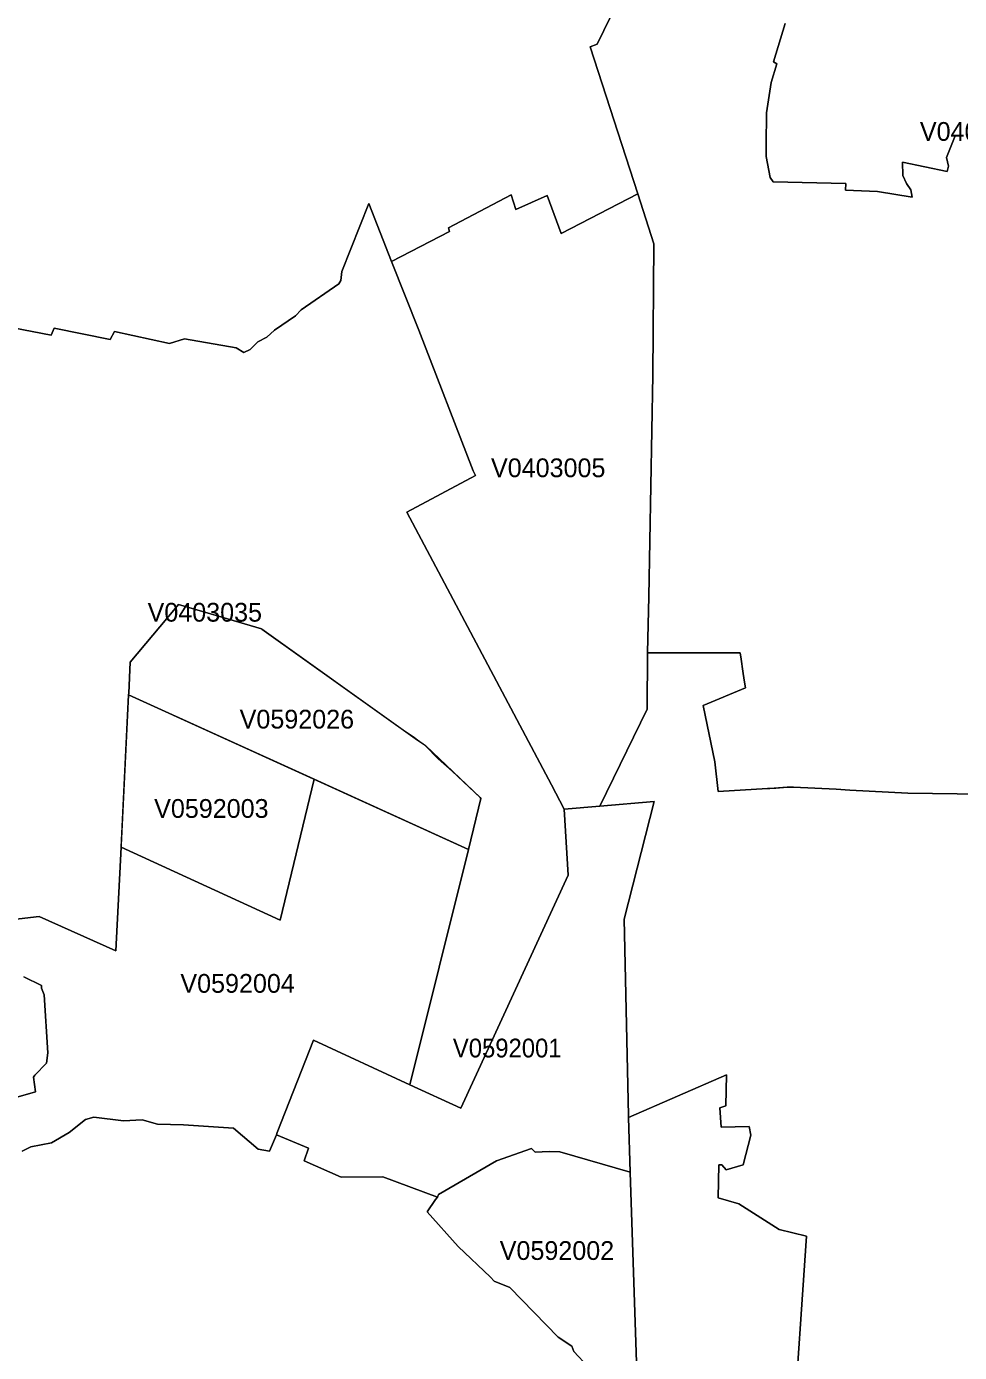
# Model space of a CAD drawing. Extents: x 369010 to 735936, y 6377141 to 6616555.
# Drawn here: x 420443 to 425415, y 6476077 to 6483144 of the extents above; entities that cross this region are included whole.
import ezdxf
from ezdxf.enums import TextEntityAlignment as Align

# ---------------------------------------------------------------- set-up
doc = ezdxf.new("R2010")
doc.units = 0
doc.header["$LTSCALE"] = 40
doc.layers.add('3', color=7, linetype='Continuous', lineweight=13)
doc.layers.add('4', color=7, linetype='Continuous')

msp = doc.modelspace()

# ---------------------------------------------------------------- linework, layer by layer
at = {"layer": '3'}
for points in [[(420168.49, 6481577.82), (420573.64, 6481498.71), (420590.69, 6481536.61), (420888.59, 6481475.2), (420911.43, 6481517.74), (421204.37, 6481454.85), (421284.81, 6481479.01), (421560.54, 6481431.84), (421600.92, 6481406.52), (421635.02, 6481422.74), (421675.4, 6481463.29), (421724.22, 6481488.11), (421764.77, 6481526.01), (421877.15, 6481601.81), (421906.61, 6481633.76), (422108.52, 6481772.78), (422118.29, 6481790.99), (422123.58, 6481837.33), (422267.74, 6482199.78), (422388.89, 6481892.11), (422698.21, 6482051.82), (422692.42, 6482070.69), (423026.08, 6482247.28), (423050.9, 6482169), (423218.06, 6482242.65), (423292.37, 6482041.23), (423700.67, 6482252.25), (423447.12, 6483035.08), (423484.69, 6483050.47), (423555.19, 6483195.45)], [(423555.19, 6483195.45), (423484.69, 6483050.47), (423447.12, 6483035.08), (423700.67, 6482252.25), (423787.23, 6481985.29), (423781.93, 6481286.36), (423759.92, 6480105.49), (423752.31, 6479805.6), (424246.01, 6479805.27), (424251.14, 6479771.67), (424260.9, 6479707.62), (424268.18, 6479660.29), (424274.31, 6479619.9), (424048.56, 6479524.57), (424111.29, 6479224.02), (424129.16, 6479066.96), (424392.15, 6479083.34), (424404.89, 6479082.68), (424436.01, 6479085.33), (424496.58, 6479089.46), (424530.51, 6479090.13), (424757.91, 6479079.37), (424831.56, 6479073.74), (425140.39, 6479058.35), (425534.95, 6479052.39)], [(425422.41, 6482558.92), (425392.95, 6482561.57), (425346.11, 6482445.06), (425357.2, 6482400.04), (425349.92, 6482370.58), (425111.1, 6482421.06), (425113.08, 6482350.39), (425132.45, 6482307.36), (425155.95, 6482272.77), (425163.23, 6482234.87), (424978.53, 6482265.32), (424808.39, 6482271.44), (424809.05, 6482306.7), (424421.61, 6482316.13), (424407.21, 6482338.31), (424385.69, 6482451.35), (424384.53, 6482513.58), (424387.02, 6482684.38), (424411.84, 6482845.58), (424441.63, 6482944.05), (424424.75, 6482956.3), (424486.98, 6483159.21)], [(424486.98, 6483159.21), (424424.75, 6482956.3), (424441.63, 6482944.05), (424411.84, 6482845.58), (424387.02, 6482684.38), (424384.53, 6482513.58), (424385.69, 6482451.35), (424407.21, 6482338.31), (424421.61, 6482316.13), (424809.05, 6482306.7), (424808.39, 6482271.44), (424978.53, 6482265.32), (425163.23, 6482234.87), (425155.95, 6482272.77), (425132.45, 6482307.36), (425113.08, 6482350.39), (425111.1, 6482421.06), (425349.92, 6482370.58), (425357.2, 6482400.04), (425346.11, 6482445.06), (425392.95, 6482561.57), (425422.41, 6482558.92)], [(420220.62, 6478366.87), (420511.41, 6478401.3), (420919.87, 6478217.26), (420947.18, 6478770.54), (420987.07, 6479582.67), (420987.56, 6479591.44), (420995.67, 6479755.62), (421236.98, 6480043.76), (421252.87, 6480062.79), (421253.03, 6480063.12), (421393.38, 6480022.08), (421694.76, 6479933.87), (421695.09, 6479933.87), (421697.41, 6479932.21), (422527.58, 6479340.86), (422564.32, 6479316.37), (422569.62, 6479310.91), (422571.27, 6479309.75), (422860.08, 6479035.01), (422865.21, 6479030.21), (422798.01, 6478758.29), (422486.2, 6477503.44), (422757.3, 6477378.65), (423330.27, 6478621.25), (423308.76, 6478971.79), (423241.73, 6479102.04), (422470.48, 6480554.84), (422835.58, 6480751.62), (422823.83, 6480775.12), (422533.37, 6481525.52), (422388.89, 6481892.11), (422267.74, 6482199.78), (422123.58, 6481837.33), (422118.29, 6481790.99), (422108.52, 6481772.78), (421906.61, 6481633.76), (421877.15, 6481601.81), (421764.77, 6481526.01), (421724.22, 6481488.11), (421675.4, 6481463.29), (421635.02, 6481422.74), (421600.92, 6481406.52), (421560.54, 6481431.84), (421284.81, 6481479.01), (421204.37, 6481454.85), (420911.43, 6481517.74), (420888.59, 6481475.2), (420590.69, 6481536.61), (420573.64, 6481498.71), (420168.49, 6481577.82)], [(423752.31, 6479805.43), (423751.48, 6479505.71), (423499.09, 6478988.18), (423788.06, 6479013.83), (423628.84, 6478386.07), (423650.69, 6477340.58), (423651.02, 6477330.16), (424174.51, 6477556.07), (424169.38, 6477391.23), (424138.1, 6477380.8), (424146.04, 6477278.35), (424294.5, 6477280.84), (424303.77, 6477235.16), (424262.89, 6477076.6), (424171.53, 6477050.46), (424148.03, 6477076.6), (424132.31, 6477076.6), (424130.15, 6476901.67), (424239.55, 6476869.39), (424453.71, 6476732.19), (424600.35, 6476696.77), (424528.03, 6475631.92)], [(425534.95, 6479052.39), (425140.39, 6479058.35), (424831.56, 6479073.74), (424757.91, 6479079.37), (424530.51, 6479090.13), (424496.58, 6479089.46), (424404.89, 6479082.68), (424392.15, 6479083.34), (424129.16, 6479066.96), (424111.29, 6479224.02), (424048.56, 6479524.57), (424274.31, 6479619.9), (424268.18, 6479660.29), (424260.9, 6479707.62), (424251.14, 6479771.67), (424246.01, 6479805.1), (423752.31, 6479805.43)], [(420419.55, 6477150.75), (420466.56, 6477172.93), (420576.12, 6477193.95), (420670.13, 6477250.05), (420757.51, 6477317.91), (420802.7, 6477331.65), (420960.59, 6477312.12), (421059.72, 6477316.09), (421141.98, 6477293.75), (421280.34, 6477289.94), (421546.47, 6477273.39), (421677.05, 6477161.18), (421738.29, 6477150.75), (421774.87, 6477236.48), (421778.67, 6477249.56), (421973.31, 6477741.77), (422486.2, 6477503.44), (422486.2, 6477503.44), (422486.2, 6477503.44), (422798.01, 6478758.29), (421976.45, 6479132.33), (421976.45, 6479132.16), (421795.55, 6478380.78), (420947.18, 6478770.54), (420919.87, 6478217.26), (420511.41, 6478401.3), (420220.62, 6478366.87)], [(420198.28, 6477383.12), (420491.88, 6477465.37), (420480.13, 6477543.82), (420487.91, 6477554.25), (420550.47, 6477618.13), (420557.09, 6477674.41), (420537.56, 6477983.9), (420523.33, 6478017.83), (420523.33, 6478033.55), (420428.16, 6478078.73)], [(420428.16, 6478078.73), (420523.33, 6478033.55), (420523.33, 6478017.83), (420537.56, 6477983.9), (420557.09, 6477674.41), (420550.47, 6477618.13), (420487.91, 6477554.25), (420480.13, 6477543.82), (420491.88, 6477465.37), (420198.28, 6477383.12)], [(424528.03, 6475631.92), (424600.35, 6476696.77), (424453.71, 6476732.19), (424239.55, 6476869.39), (424130.15, 6476901.67), (424132.31, 6477076.6), (424148.03, 6477076.6), (424171.53, 6477050.46), (424262.89, 6477076.6), (424303.77, 6477235.16), (424294.5, 6477280.84), (424146.04, 6477278.35), (424138.1, 6477380.8), (424169.38, 6477391.23), (424174.51, 6477556.07), (423651.02, 6477330.16), (423660.45, 6477037.88), (423698.52, 6475863.96)], [(421280.34, 6477289.94), (421141.98, 6477293.75), (421059.72, 6477316.09), (420960.59, 6477312.12), (420802.7, 6477331.65), (420757.51, 6477317.91), (420670.13, 6477250.05), (420576.12, 6477193.95), (420466.56, 6477172.93), (420419.55, 6477150.75)], [(423436.36, 6475999.84), (423360.56, 6476082.09), (423350.13, 6476110.72), (423277.15, 6476159.05), (423018.46, 6476423.03), (422935.05, 6476457.12), (422916.68, 6476477.98), (422743.23, 6476642.49), (422578.06, 6476826.69), (422622.41, 6476893.23), (422634.16, 6476905.64), (422341.39, 6477013.55), (422119.61, 6477012.22), (421923.49, 6477098.12), (421945.67, 6477165.98), (421774.87, 6477236.48), (421738.29, 6477150.75), (421677.05, 6477161.18), (421546.47, 6477273.39), (421280.34, 6477289.94)]]:
    msp.add_lwpolyline(points, dxfattribs=at)
for points in [[(423700.67, 6482252.25), (423292.37, 6482041.23), (423218.06, 6482242.65), (423050.9, 6482169), (423026.08, 6482247.28), (422692.42, 6482070.69), (422698.21, 6482051.82), (422388.89, 6481892.11), (422533.37, 6481525.52), (422823.83, 6480775.12), (422835.58, 6480751.62), (422470.48, 6480554.84), (423241.73, 6479102.04), (423308.76, 6478971.79), (423499.09, 6478988.18), (423751.48, 6479505.71), (423752.31, 6479805.43), (423759.92, 6480105.49), (423781.93, 6481286.36), (423787.23, 6481985.29)], [(420995.67, 6479755.62), (420987.56, 6479591.44), (420987.07, 6479582.67), (422798.01, 6478758.29), (422486.2, 6477503.44), (422486.2, 6477503.44), (422798.01, 6478758.29), (422865.21, 6479030.21), (422861.07, 6479034.02), (422860.08, 6479035.01), (422711.95, 6479175.69), (422637.64, 6479241.07), (422569.62, 6479310.91), (422527.58, 6479340.86), (422510.7, 6479352.12), (422451.12, 6479393.83), (421697.41, 6479932.21), (421695.09, 6479933.87), (421694.76, 6479933.87), (421393.38, 6480022.08), (421253.03, 6480063.12), (421252.87, 6480062.79), (421236.98, 6480043.76)], [(420987.07, 6479582.67), (420947.51, 6478780.3), (420947.51, 6478777.32), (420947.18, 6478770.54), (421795.55, 6478380.78), (421976.45, 6479132.16), (421976.45, 6479132.33)], [(423499.09, 6478988.18), (423308.76, 6478971.79), (423330.27, 6478621.25), (422757.3, 6477378.65), (422486.2, 6477503.44), (421973.31, 6477741.77), (421778.67, 6477249.56), (421774.87, 6477236.48), (421945.67, 6477165.98), (421923.49, 6477098.12), (422119.61, 6477012.22), (422341.39, 6477013.55), (422634.16, 6476905.64), (422637.97, 6476918.71), (422947.3, 6477099.28), (423135.14, 6477163.33), (423153.52, 6477143.8), (423229.15, 6477147.61), (423285.26, 6477146.28), (423660.45, 6477037.88), (423651.02, 6477330.16), (423650.69, 6477340.58), (423628.84, 6478386.07), (423788.06, 6479013.83)], [(422634.16, 6476905.64), (422622.41, 6476893.23), (422578.06, 6476826.69), (422743.23, 6476642.49), (422916.68, 6476477.98), (422935.05, 6476457.12), (423018.46, 6476423.03), (423277.15, 6476159.05), (423350.13, 6476110.72), (423360.56, 6476082.09), (423436.36, 6475999.84), (423446.79, 6475933.14), (423526.89, 6475869.42), (423574.89, 6475848.57), (423688.59, 6475825.06), (423698.52, 6475863.96), (423660.45, 6477037.88), (423285.26, 6477146.28), (423229.15, 6477147.61), (423153.52, 6477143.8), (423135.14, 6477163.33), (422947.3, 6477099.28), (422637.97, 6476918.71)]]:
    msp.add_lwpolyline(points, close=True, dxfattribs=at)

# ---------------------------------------------------------------- texts
at = {"layer": '4'}
for s, p in [('V0403006', (425509.32, 6482534.47)), ('V0403005', (423223.51, 6480741.91)), ('V0403035', (421393.38, 6479972.08)), ('V0592026', (421883.98, 6479402.28)), ('V0592003', (421428.3, 6478926.38)), ('V0592004', (421568.11, 6477994.17)), ('V0592002', (423270.14, 6476570.36))]:
    msp.add_text(s, height=100, dxfattribs=at).set_placement(p, align=Align.CENTER)
at = {"layer": '4', "width": 0.95}
msp.add_text('V0592001', height=100, dxfattribs=at).set_placement((423005.06, 6477649.58), align=Align.CENTER)

doc.saveas('drawing.dxf')
